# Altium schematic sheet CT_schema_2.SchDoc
size 400 x 230 mm
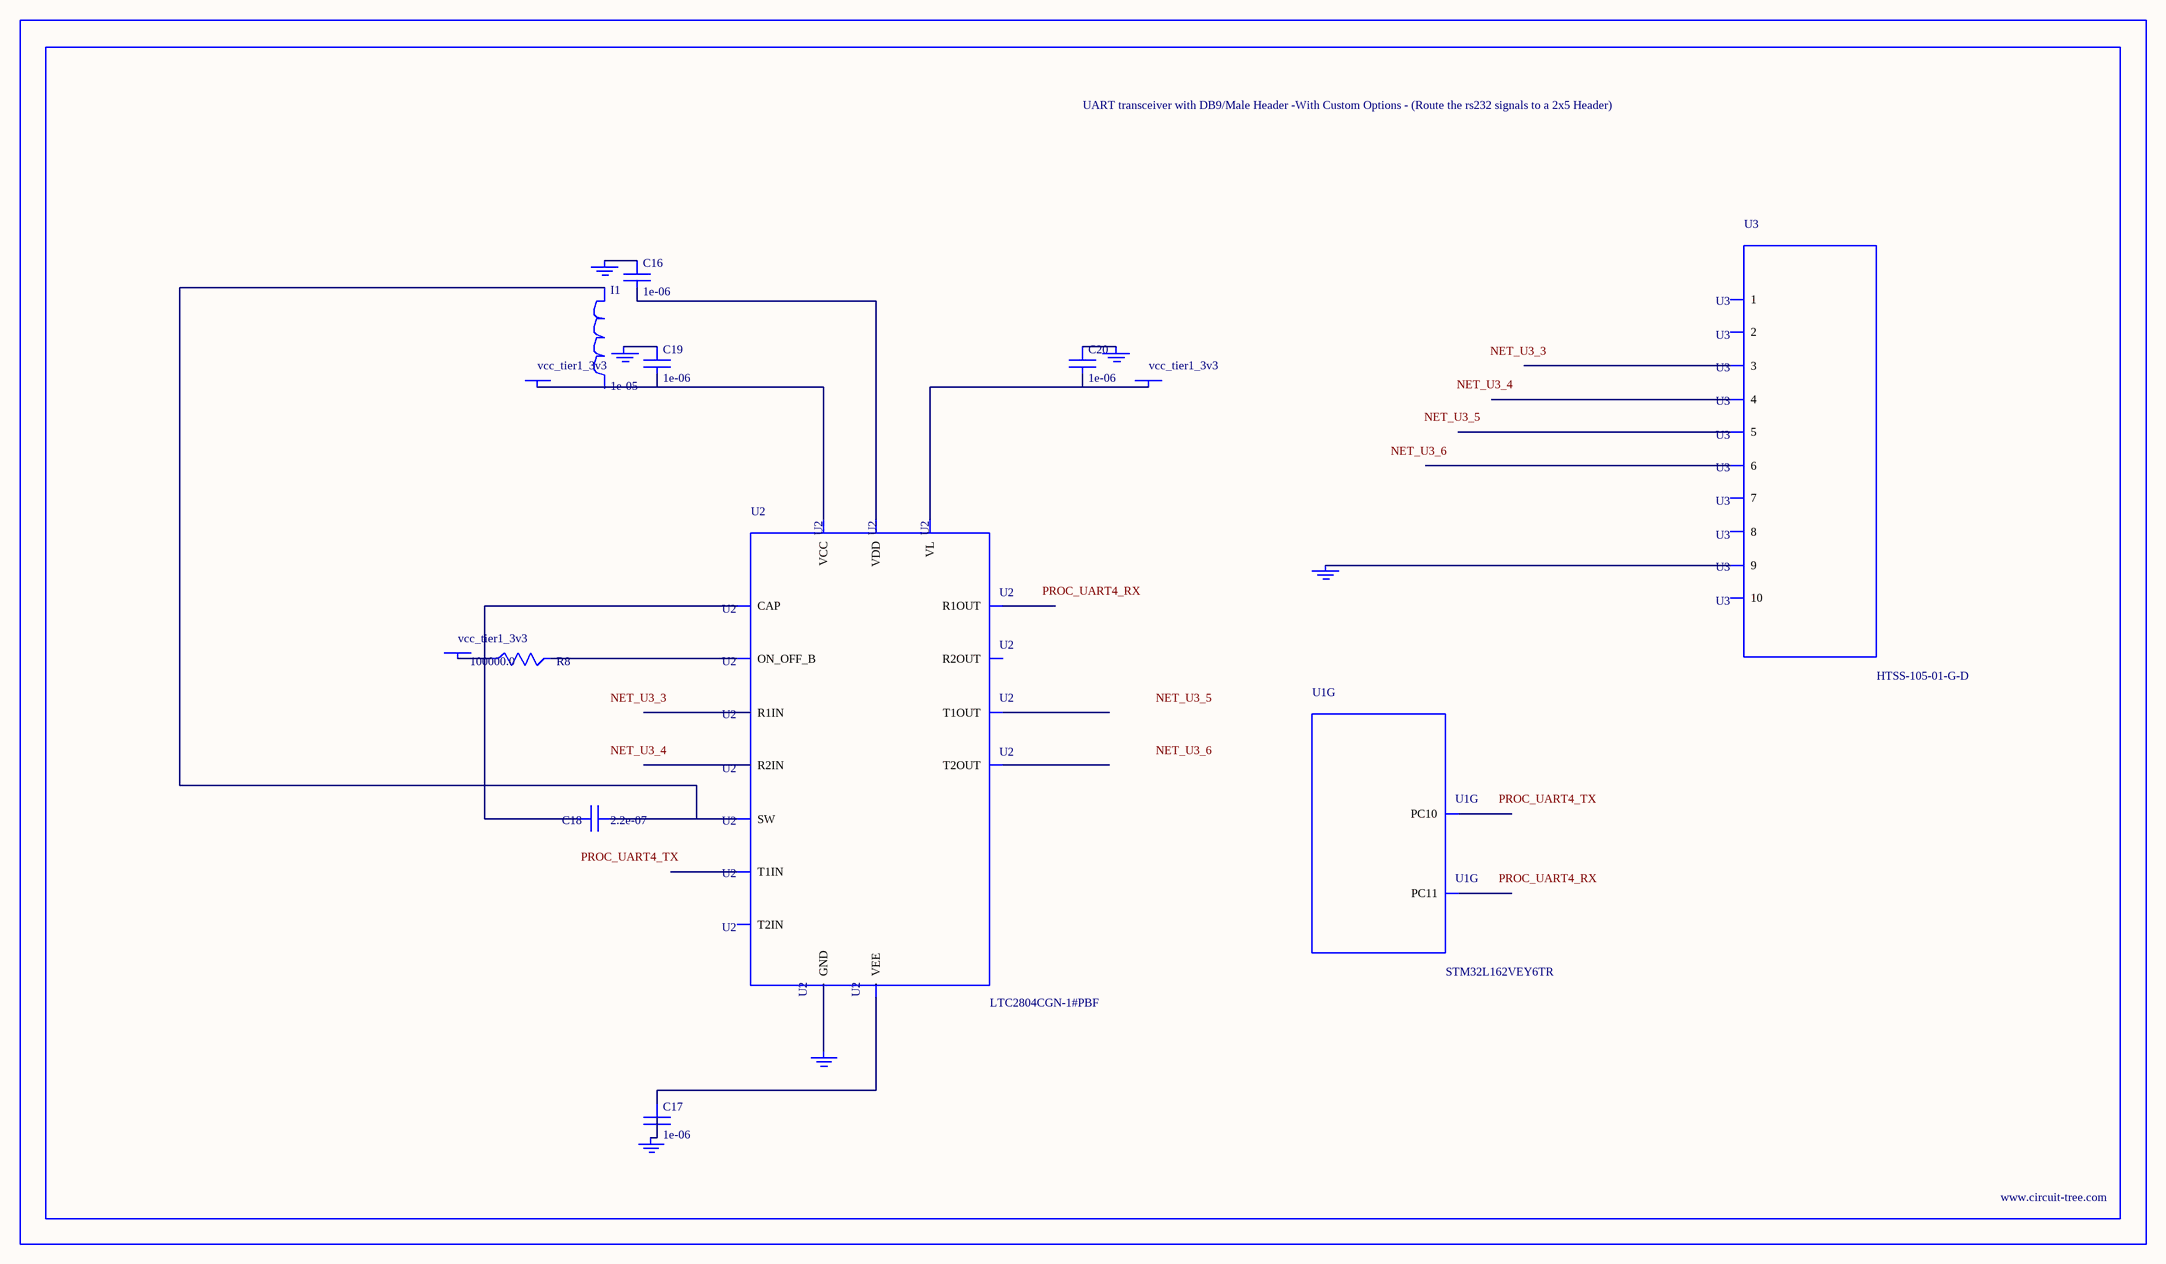
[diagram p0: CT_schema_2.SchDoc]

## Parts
BORDER1  (no value)
C16  1e-06  [C0603]
C17  1e-06  [C0603]
C18  2.2e-07  [C0603]
C19  1e-06  [C0603]
C20  1e-06  [C0603]
GND_INSTANCE_1_0  (no value)
GND_INSTANCE_1_1  (no value)
GND_INSTANCE_1_2  (no value)
GND_INSTANCE_1_3  (no value)
GND_INSTANCE_1_4  (no value)
GND_INSTANCE_1_5  (no value)
I1  1e-05  [L1210]
POWER_INSTANCE_1_0  vcc_tier1_3v3
POWER_INSTANCE_1_1  vcc_tier1_3v3
POWER_INSTANCE_1_2  vcc_tier1_3v3
R8  100000.0  [R0603]
U1  STM32L162VEY6TR  [WLCSP104]  (part G of 9)
U2  LTC2804CGN-1#PBF  [SSOP-16]
U3  HTSS-105-01-G-D  [HTSS-105-01-G-D]

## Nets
NetC16_1: C16.1 GND_INSTANCE_1_1.0(GND)
NetC16_2: C16.2 U2.6(VDD)
NetC17_1: C17.1 U2.9(VEE)
NetC17_2: C17.2 GND_INSTANCE_1_2.0(GND)
NetC18_1: C18.1 I1.1 U2.7(SW)
NetC18_2: C18.2 U2.10(CAP)
NetC19_1: C19.1 GND_INSTANCE_1_0.0(GND)
NetC19_2: C19.2 POWER_INSTANCE_1_0.0(PWR) U2.5(VCC)
NetC20_1: C20.1 GND_INSTANCE_1_3.0(GND)
NetC20_2: C20.2 POWER_INSTANCE_1_2.0(PWR) U2.12(VL)
NetGND_INSTANCE_1_4_0: GND_INSTANCE_1_4.0(GND) U2.8(GND)
NetGND_INSTANCE_1_5_0: GND_INSTANCE_1_5.0(GND) U3.9
NetPOWER_INSTANCE_1_1_0: POWER_INSTANCE_1_1.0(PWR) R8.1
NetR8_2: R8.2 U2.11(ON_OFF_B)

Not connected (* = marked no-connect by the designer): I1 2; U1 C2(PC11) E4(PC10); U2 1(R1IN) 2(R2IN) 3(T1OUT) 4(T2OUT) 13(T2IN) 14(T1IN) 15(R2OUT) 16(R1OUT); U3 1 2 3 4 5 6 7 8 10

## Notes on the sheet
- Labels drawn without touching a wire or pin: NET_U3_3, NET_U3_4, NET_U3_5, NET_U3_6, PROC_UART4_RX, PROC_UART4_TX

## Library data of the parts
BORDER1 = BORDER_PAGE1
C16 C17 C19 C20 = C0603C105K3RACTU
C18 = C0603C224K3RAC
GND_INSTANCE_1_0-GND_INSTANCE_1_5 = GND
I1 = CBC3225T100MR
POWER_INSTANCE_1_0-POWER_INSTANCE_1_2 = PWR
R8 = RC0603JR-07100KL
